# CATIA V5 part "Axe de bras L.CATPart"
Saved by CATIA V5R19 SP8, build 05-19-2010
Part number: Axe de bras L
Revision: ANY
Definition: UNKNOWN
Nomenclature: Axe de bras L
Source: Unknown
Bounding box of the stored display mesh (mm): x -3.49 to 3.49, y -4 to 5.5, z -3.5 to 3.5
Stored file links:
  D:\Documents\1_Travail\1 - ac-limoges.fr\OneDrive - ac-limoges.fr\STI2D_Turgot\2 -2I2D\3_SEQUENCE_Serre_Connectée\3- Spécificités\ITEC\EC 3 Ouverture automatique\Simulation  Ouverture Automatique\Axe de bras L.CATPart
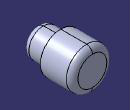
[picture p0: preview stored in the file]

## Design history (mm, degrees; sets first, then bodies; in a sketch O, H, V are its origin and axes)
Body1 "NONE" (main body)
  Solid1: solid without history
